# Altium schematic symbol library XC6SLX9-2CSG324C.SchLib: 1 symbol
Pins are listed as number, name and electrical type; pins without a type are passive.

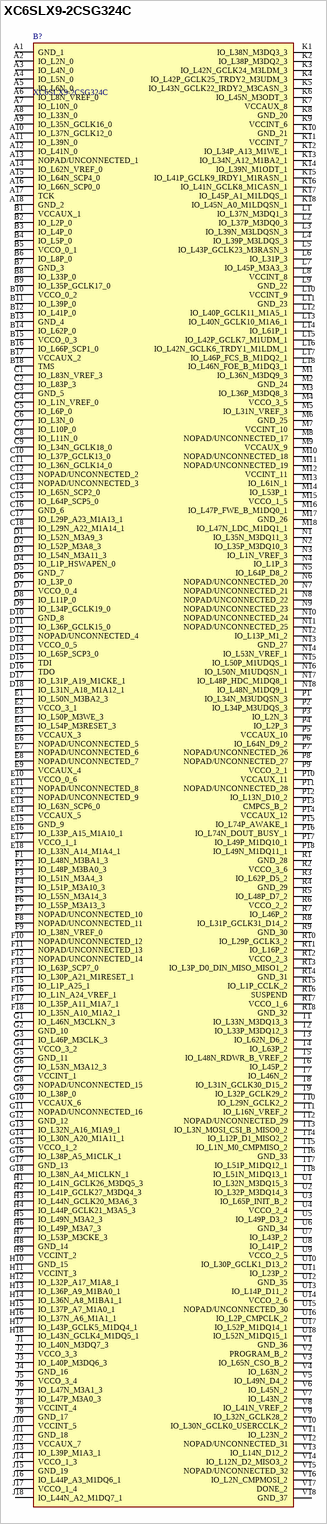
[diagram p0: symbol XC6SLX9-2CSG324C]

## XC6SLX9-2CSG324C
designator B?
FPGA - Field Programmable Gate Array XC6SLX9-2CSG324C; Manufacturer_Name: AMD; Geometry.Height: 1.5mm
footprint BGA324C80P18X18_1500X1500X150
pins: A1 GND_1, A2 IO_L2N_0, A3 IO_L4N_0, A4 IO_L5N_0, A5 IO_L6N_0, A6 IO_L8N_VREF_0, A7 IO_L10N_0, A8 IO_L33N_0, A9 IO_L35N_GCLK16_0, A10 IO_L37N_GCLK12_0, A11 IO_L39N_0, A12 IO_L41N_0, A13 NOPAD/UNCONNECTED_1, A14 IO_L62N_VREF_0, A15 IO_L64N_SCP4_0, A16 IO_L66N_SCP0_0, A17 TCK, A18 GND_2, B1 VCCAUX_1, B2 IO_L2P_0, B3 IO_L4P_0, B4 IO_L5P_0, B5 VCCO_0_1, B6 IO_L8P_0, B7 GND_3, B8 IO_L33P_0, B9 IO_L35P_GCLK17_0, B10 VCCO_0_2, B11 IO_L39P_0, B12 IO_L41P_0, B13 GND_4, B14 IO_L62P_0, B15 VCCO_0_3, B16 IO_L66P_SCP1_0, B17 VCCAUX_2, B18 TMS, C1 IO_L83N_VREF_3, C2 IO_L83P_3, C3 GND_5, C4 IO_L1N_VREF_0, C5 IO_L6P_0, C6 IO_L3N_0, C7 IO_L10P_0, C8 IO_L11N_0, C9 IO_L34N_GCLK18_0, C10 IO_L37P_GCLK13_0, C11 IO_L36N_GCLK14_0, C12 NOPAD/UNCONNECTED_2, C13 NOPAD/UNCONNECTED_3, C14 IO_L65N_SCP2_0, C15 IO_L64P_SCP5_0, C16 GND_6, C17 IO_L29P_A23_M1A13_1, C18 IO_L29N_A22_M1A14_1, D1 IO_L52N_M3A9_3, D2 IO_L52P_M3A8_3, D3 IO_L54N_M3A11_3, D4 IO_L1P_HSWAPEN_0, D5 GND_7, D6 IO_L3P_0, D7 VCCO_0_4, D8 IO_L11P_0, D9 IO_L34P_GCLK19_0, D10 GND_8, D11 IO_L36P_GCLK15_0, D12 NOPAD/UNCONNECTED_4, D13 VCCO_0_5, D14 IO_L65P_SCP3_0, D15 TDI, D16 TDO, D17 IO_L31P_A19_M1CKE_1, D18 IO_L31N_A18_M1A12_1, E1 IO_L50N_M3BA2_3, E2 VCCO_3_1, E3 IO_L50P_M3WE_3, E4 IO_L54P_M3RESET_3, E5 VCCAUX_3, E6 NOPAD/UNCONNECTED_5, E7 NOPAD/UNCONNECTED_6, E8 NOPAD/UNCONNECTED_7, E9 VCCAUX_4, E10 VCCO_0_6, E11 NOPAD/UNCONNECTED_8, E12 NOPAD/UNCONNECTED_9, E13 IO_L63N_SCP6_0, E14 VCCAUX_5, E15 GND_9, E16 IO_L33P_A15_M1A10_1, E17 VCCO_1_1, E18 IO_L33N_A14_M1A4_1, F1 IO_L48N_M3BA1_3, F2 IO_L48P_M3BA0_3, F3 IO_L51N_M3A4_3, F4 IO_L51P_M3A10_3, F5 IO_L55N_M3A14_3, F6 IO_L55P_M3A13_3, F7 NOPAD/UNCONNECTED_10, F8 NOPAD/UNCONNECTED_11, F9 IO_L38N_VREF_0, F10 NOPAD/UNCONNECTED_12, F11 NOPAD/UNCONNECTED_13, F12 NOPAD/UNCONNECTED_14, F13 IO_L63P_SCP7_0, F14 IO_L30P_A21_M1RESET_1, F15 IO_L1P_A25_1, F16 IO_L1N_A24_VREF_1, F17 IO_L35P_A11_M1A7_1, F18 IO_L35N_A10_M1A2_1, G1 IO_L46N_M3CLKN_3, G2 GND_10, G3 IO_L46P_M3CLK_3, G4 VCCO_3_2, G5 GND_11, G6 IO_L53N_M3A12_3, G7 VCCINT_1, G8 NOPAD/UNCONNECTED_15, G9 IO_L38P_0, G10 VCCAUX_6, G11 NOPAD/UNCONNECTED_16, G12 GND_12, G13 IO_L32N_A16_M1A9_1, G14 IO_L30N_A20_M1A11_1, G15 VCCO_1_2, G16 IO_L38P_A5_M1CLK_1, G17 GND_13, G18 IO_L38N_A4_M1CLKN_1, H1 IO_L41N_GCLK26_M3DQ5_3, H2 IO_L41P_GCLK27_M3DQ4_3, H3 IO_L44N_GCLK20_M3A6_3, H4 IO_L44P_GCLK21_M3A5_3, H5 IO_L49N_M3A2_3, H6 IO_L49P_M3A7_3, H7 IO_L53P_M3CKE_3, H8 GND_14, H9 VCCINT_2, H10 GND_15, H11 VCCINT_3, H12 IO_L32P_A17_M1A8_1, H13 IO_L36P_A9_M1BA0_1, H14 IO_L36N_A8_M1BA1_1, H15 IO_L37P_A7_M1A0_1, H16 IO_L37N_A6_M1A1_1, H17 IO_L43P_GCLK5_M1DQ4_1, H18 IO_L43N_GCLK4_M1DQ5_1, J1 IO_L40N_M3DQ7_3, J2 VCCO_3_3, J3 IO_L40P_M3DQ6_3, J4 GND_16, J5 VCCO_3_4, J6 IO_L47N_M3A1_3, J7 IO_L47P_M3A0_3, J8 VCCINT_4, J9 GND_17, J10 VCCINT_5, J11 GND_18, J12 VCCAUX_7, J13 IO_L39P_M1A3_1, J14 VCCO_1_3, J15 GND_19, J16 IO_L44P_A3_M1DQ6_1, J17 VCCO_1_4, J18 IO_L44N_A2_M1DQ7_1, K1 IO_L38N_M3DQ3_3, K2 IO_L38P_M3DQ2_3, K3 IO_L42N_GCLK24_M3LDM_3, K4 IO_L42P_GCLK25_TRDY2_M3UDM_3, K5 IO_L43N_GCLK22_IRDY2_M3CASN_3, K6 IO_L45N_M3ODT_3, K7 VCCAUX_8, K8 GND_20, K9 VCCINT_6, K10 GND_21, K11 VCCINT_7, K12 IO_L34P_A13_M1WE_1, K13 IO_L34N_A12_M1BA2_1, K14 IO_L39N_M1ODT_1, K15 IO_L41P_GCLK9_IRDY1_M1RASN_1, K16 IO_L41N_GCLK8_M1CASN_1, K17 IO_L45P_A1_M1LDQS_1, K18 IO_L45N_A0_M1LDQSN_1, L1 IO_L37N_M3DQ1_3, L2 IO_L37P_M3DQ0_3, L3 IO_L39N_M3LDQSN_3, L4 IO_L39P_M3LDQS_3, L5 IO_L43P_GCLK23_M3RASN_3, L6 IO_L31P_3, L7 IO_L45P_M3A3_3, L8 VCCINT_8, L9 GND_22, L10 VCCINT_9, L11 GND_23, L12 IO_L40P_GCLK11_M1A5_1, L13 IO_L40N_GCLK10_M1A6_1, L14 IO_L61P_1, L15 IO_L42P_GCLK7_M1UDM_1, L16 IO_L42N_GCLK6_TRDY1_M1LDM_1, L17 IO_L46P_FCS_B_M1DQ2_1, L18 IO_L46N_FOE_B_M1DQ3_1, M1 IO_L36N_M3DQ9_3, M2 GND_24, M3 IO_L36P_M3DQ8_3, M4 VCCO_3_5, M5 IO_L31N_VREF_3, M6 GND_25, M7 VCCINT_10, M8 NOPAD/UNCONNECTED_17, M9 VCCAUX_9, M10 NOPAD/UNCONNECTED_18, M11 NOPAD/UNCONNECTED_19, M12 VCCINT_11, M13 IO_L61N_1, M14 IO_L53P_1, M15 VCCO_1_5, M16 IO_L47P_FWE_B_M1DQ0_1, M17 GND_26, M18 IO_L47N_LDC_M1DQ1_1, N1 IO_L35N_M3DQ11_3, N2 IO_L35P_M3DQ10_3, N3 IO_L1N_VREF_3, N4 IO_L1P_3, N5 IO_L64P_D8_2, N6 NOPAD/UNCONNECTED_20, N7 NOPAD/UNCONNECTED_21, N8 NOPAD/UNCONNECTED_22, N9 NOPAD/UNCONNECTED_23, N10 NOPAD/UNCONNECTED_24, N11 NOPAD/UNCONNECTED_25, N12 IO_L13P_M1_2, N13 GND_27, N14 IO_L53N_VREF_1, N15 IO_L50P_M1UDQS_1, N16 IO_L50N_M1UDQSN_1, N17 IO_L48P_HDC_M1DQ8_1, N18 IO_L48N_M1DQ9_1, P1 IO_L34N_M3UDQSN_3, P2 IO_L34P_M3UDQS_3, P3 IO_L2N_3, P4 IO_L2P_3, P5 VCCAUX_10, P6 IO_L64N_D9_2, P7 NOPAD/UNCONNECTED_26, P8 NOPAD/UNCONNECTED_27, P9 VCCO_2_1, P10 VCCAUX_11, P11 NOPAD/UNCONNECTED_28, P12 IO_L13N_D10_2, P13 CMPCS_B_2, P14 VCCAUX_12, P15 IO_L74P_AWAKE_1, P16 IO_L74N_DOUT_BUSY_1, P17 IO_L49P_M1DQ10_1, P18 IO_L49N_M1DQ11_1, R1 GND_28, R2 VCCO_3_6, R3 IO_L62P_D5_2, R4 GND_29, R5 IO_L48P_D7_2, R6 VCCO_2_2, R7 IO_L46P_2, R8 IO_L31P_GCLK31_D14_2, R9 GND_30, R10 IO_L29P_GCLK3_2, R11 IO_L16P_2, R12 VCCO_2_3, R13 IO_L3P_D0_DIN_MISO_MISO1_2, R14 GND_31, R15 IO_L1P_CCLK_2, R16 SUSPEND, R17 VCCO_1_6, R18 GND_32, T1 IO_L33N_M3DQ13_3, T2 IO_L33P_M3DQ12_3, T3 IO_L62N_D6_2, T4 IO_L63P_2, T5 IO_L48N_RDWR_B_VREF_2, T6 IO_L45P_2, T7 IO_L46N_2, T8 IO_L31N_GCLK30_D15_2, T9 IO_L32P_GCLK29_2, T10 IO_L29N_GCLK2_2, T11 IO_L16N_VREF_2, T12 NOPAD/UNCONNECTED_29, T13 IO_L3N_MOSI_CSI_B_MISO0_2, T14 IO_L12P_D1_MISO2_2, T15 IO_L1N_M0_CMPMISO_2, T16 GND_33, T17 IO_L51P_M1DQ12_1, T18 IO_L51N_M1DQ13_1, U1 IO_L32N_M3DQ15_3, U2 IO_L32P_M3DQ14_3, U3 IO_L65P_INIT_B_2, U4 VCCO_2_4, U5 IO_L49P_D3_2, U6 GND_34, U7 IO_L43P_2, U8 IO_L41P_2, U9 VCCO_2_5, U10 IO_L30P_GCLK1_D13_2, U11 IO_L23P_2, U12 GND_35, U13 IO_L14P_D11_2, U14 VCCO_2_6, U15 NOPAD/UNCONNECTED_30, U16 IO_L2P_CMPCLK_2, U17 IO_L52P_M1DQ14_1, U18 IO_L52N_M1DQ15_1, V1 GND_36, V2 PROGRAM_B_2, V3 IO_L65N_CSO_B_2, V4 IO_L63N_2, V5 IO_L49N_D4_2, V6 IO_L45N_2, V7 IO_L43N_2, V8 IO_L41N_VREF_2, V9 IO_L32N_GCLK28_2, V10 IO_L30N_GCLK0_USERCCLK_2, V11 IO_L23N_2, V12 NOPAD/UNCONNECTED_31, V13 IO_L14N_D12_2, V14 IO_L12N_D2_MISO3_2, V15 NOPAD/UNCONNECTED_32, V16 IO_L2N_CMPMOSI_2, V17 DONE_2, V18 GND_37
